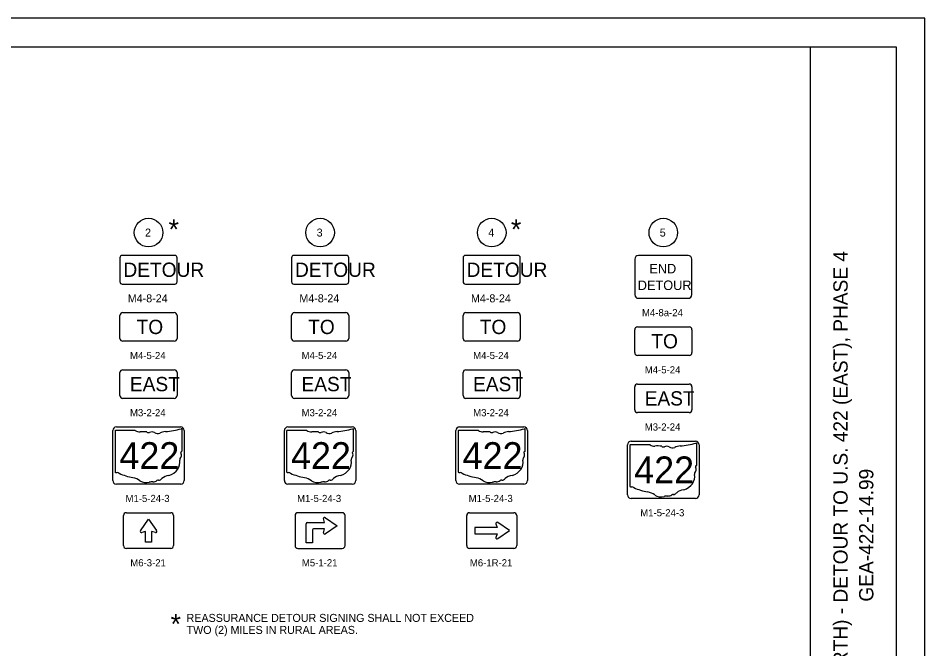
# Model space of a CAD drawing. Extents: x -0.3 to 34, y 0 to 22.
# Drawn here: x 18.15 to 34, y 10.97 to 22 of the extents above; entities that cross this region are included whole.
import ezdxf

# ---------------------------------------------------------------- set-up
doc = ezdxf.new("R2010")
doc.units = 0
for name, color, linetype in [('GM_X_Adjacent_County_Text', 7, 'Continuous'), ('GM_X_County', 7, 'Continuous'), ('GM_X_Minor_Lake_Text', 7, 'Continuous'), ('GM_X_Minor_River_Text', 7, 'Continuous'), ('GM_X_Section', 7, 'Continuous'), ('GM_X_Township', 7, 'Continuous')]:
    doc.layers.add(name, color=color, linetype=linetype)

msp = doc.modelspace()

# ---------------------------------------------------------------- linework, layer by layer
at = {"layer": 'GM_X_County'}
msp.add_line((32, 0.5), (32, 21.5), dxfattribs=at)
msp.add_lwpolyline([(1.5, 21.5), (33.5, 21.5), (33.5, 0.5), (1.5, 0.5)], close=True, dxfattribs=at)
at = {"layer": 'GM_X_Minor_Lake_Text'}
for centre in [(20.427, 18.249), (23.427, 18.249), (26.427, 18.249), (29.427, 18.249)]:
    msp.add_circle(centre, 0.25, dxfattribs=at)
at = {"layer": 'GM_X_Minor_River_Text'}
for p, q in [((19.977, 16.849), (20.877, 16.849)), ((22.977, 16.849), (23.877, 16.849)), ((25.977, 16.849), (26.877, 16.849)), ((19.927, 16.399), (19.927, 16.799)), ((20.927, 16.799), (20.927, 16.399)), ((22.927, 16.399), (22.927, 16.799)), ((23.927, 16.799), (23.927, 16.399)), ((25.927, 16.399), (25.927, 16.799)), ((26.927, 16.799), (26.927, 16.399)), ((28.927, 16.149), (28.927, 16.549)), ((28.977, 16.599), (29.877, 16.599)), ((29.927, 16.549), (29.927, 16.149)), ((20.877, 16.349), (19.977, 16.349)), ((23.877, 16.349), (22.977, 16.349)), ((26.877, 16.349), (25.977, 16.349)), ((29.877, 16.099), (28.977, 16.099)), ((19.927, 15.399), (19.927, 15.799)), ((19.977, 15.849), (20.877, 15.849)), ((20.927, 15.799), (20.927, 15.399)), ((22.927, 15.399), (22.927, 15.799)), ((22.977, 15.849), (23.877, 15.849)), ((23.927, 15.799), (23.927, 15.399)), ((25.927, 15.399), (25.927, 15.799)), ((25.977, 15.849), (26.877, 15.849)), ((26.927, 15.799), (26.927, 15.399)), ((28.927, 15.149), (28.927, 15.549)), ((28.977, 15.599), (29.877, 15.599)), ((29.927, 15.549), (29.927, 15.149)), ((20.877, 15.349), (19.977, 15.349)), ((23.877, 15.349), (22.977, 15.349)), ((26.877, 15.349), (25.977, 15.349)), ((29.877, 15.099), (28.977, 15.099)), ((19.841, 14.775), (19.841, 14.063)), ((20.196, 14.787), (19.852, 14.787)), ((21.013, 14.433), (21.013, 14.805)), ((22.841, 14.775), (22.841, 14.063)), ((23.196, 14.787), (22.852, 14.787)), ((24.013, 14.433), (24.013, 14.805)), ((25.841, 14.775), (25.841, 14.063)), ((26.196, 14.787), (25.852, 14.787)), ((27.013, 14.433), (27.013, 14.805)), ((21.013, 14.433), (21.013, 14.433)), ((24.013, 14.433), (24.013, 14.433)), ((27.013, 14.433), (27.013, 14.433)), ((28.841, 14.525), (28.841, 13.813)), ((29.196, 14.537), (28.852, 14.537)), ((30.013, 14.183), (30.013, 14.555)), ((30.013, 14.183), (30.013, 14.183)), ((20.039, 13.349), (20.814, 13.349)), ((23.814, 13.349), (23.039, 13.349)), ((26.039, 13.349), (26.814, 13.349)), ((19.989, 12.774), (19.989, 13.299)), ((20.285, 13.032), (20.427, 13.239)), ((20.427, 13.239), (20.567, 13.035)), ((20.864, 13.299), (20.864, 12.774)), ((22.989, 13.299), (22.989, 12.774)), ((23.208, 13.177), (23.505, 13.177)), ((23.208, 13.177), (23.208, 13.177)), ((23.505, 13.177), (23.484, 13.247)), ((23.52, 13.262), (23.724, 13.122)), ((23.864, 12.774), (23.864, 13.299)), ((25.989, 12.774), (25.989, 13.299)), ((26.739, 13.036), (26.532, 13.178)), ((26.864, 13.299), (26.864, 12.774)), ((20.372, 13.02), (20.308, 13)), ((20.372, 12.833), (20.372, 13.02)), ((20.546, 13), (20.481, 13.02)), ((20.481, 13.02), (20.481, 12.833)), ((23.185, 12.825), (23.185, 13.153)), ((23.294, 13.052), (23.294, 12.825)), ((23.505, 13.067), (23.31, 13.067)), ((23.484, 12.997), (23.505, 13.067)), ((23.724, 13.122), (23.52, 12.982)), ((26.521, 13.091), (26.13, 13.091)), ((26.13, 13.091), (26.13, 12.981)), ((26.501, 13.155), (26.521, 13.091)), ((26.535, 12.896), (26.739, 13.036)), ((26.13, 12.981), (26.521, 12.981)), ((26.521, 12.981), (26.501, 12.917)), ((20.814, 12.724), (20.039, 12.724)), ((20.481, 12.833), (20.372, 12.833)), ((23.039, 12.724), (23.814, 12.724)), ((23.294, 12.825), (23.185, 12.825)), ((26.814, 12.724), (26.039, 12.724))]:
    msp.add_line(p, q, dxfattribs=at)
for points in [[(19.927, 17.809), (19.927, 17.389)], [(20.887, 17.849), (19.967, 17.849)], [(20.927, 17.389), (20.927, 17.809)], [(22.927, 17.809), (22.927, 17.389)], [(23.887, 17.849), (22.967, 17.849)], [(23.927, 17.389), (23.927, 17.809)], [(25.927, 17.809), (25.927, 17.389)], [(26.887, 17.849), (25.967, 17.849)], [(26.927, 17.389), (26.927, 17.809)], [(28.927, 17.784), (28.927, 17.164)], [(29.862, 17.849), (28.992, 17.849)], [(29.927, 17.164), (29.927, 17.784)], [(19.967, 17.349), (20.887, 17.349)], [(22.967, 17.349), (23.887, 17.349)], [(25.967, 17.349), (26.887, 17.349)], [(28.992, 17.099), (29.862, 17.099)], [(19.802, 13.911), (19.802, 14.786)], [(19.864, 14.849), (20.989, 14.849)], [(21.052, 14.786), (21.052, 13.911)], [(22.802, 13.911), (22.802, 14.786)], [(22.864, 14.849), (23.989, 14.849)], [(24.052, 14.786), (24.052, 13.911)], [(25.802, 13.911), (25.802, 14.786)], [(25.864, 14.849), (26.989, 14.849)], [(27.052, 14.786), (27.052, 13.911)], [(28.864, 14.599), (29.989, 14.599)], [(28.802, 13.661), (28.802, 14.536)], [(30.052, 14.536), (30.052, 13.661)], [(20.989, 13.849), (19.864, 13.849)], [(23.989, 13.849), (22.864, 13.849)], [(26.989, 13.849), (25.864, 13.849)], [(29.989, 13.599), (28.864, 13.599)]]:
    msp.add_lwpolyline(points, dxfattribs=at)
for centre, radius, start, end in [((19.967, 17.809), 0.04, 90, 180), ((20.887, 17.809), 0.04, 0, 90), ((22.967, 17.809), 0.04, 90, 180), ((23.887, 17.809), 0.04, 0, 90), ((25.967, 17.809), 0.04, 90, 180), ((26.887, 17.809), 0.04, 0, 90), ((28.992, 17.784), 0.065, 90, 180), ((29.862, 17.784), 0.065, 0, 90), ((19.967, 17.389), 0.04, 180, 270), ((20.887, 17.389), 0.04, 270, 0), ((22.967, 17.389), 0.04, 180, 270), ((23.887, 17.389), 0.04, 270, 0), ((25.967, 17.389), 0.04, 180, 270), ((26.887, 17.389), 0.04, 270, 0), ((28.992, 17.164), 0.065, 180, 270), ((29.862, 17.164), 0.065, 270, 0), ((19.977, 16.799), 0.05, 90, 180), ((20.877, 16.799), 0.05, 0, 90), ((22.977, 16.799), 0.05, 90, 180), ((23.877, 16.799), 0.05, 0, 90), ((25.977, 16.799), 0.05, 90, 180), ((26.877, 16.799), 0.05, 0, 90), ((28.977, 16.549), 0.05, 90, 180), ((29.877, 16.549), 0.05, 0, 90), ((19.977, 16.399), 0.05, 180, 270), ((20.877, 16.399), 0.05, 270, 360), ((22.977, 16.399), 0.05, 180, 270), ((23.877, 16.399), 0.05, 270, 360), ((25.977, 16.399), 0.05, 180, 270), ((26.877, 16.399), 0.05, 270, 360), ((28.977, 16.149), 0.05, 180, 270), ((29.877, 16.149), 0.05, 270, 360), ((19.977, 15.799), 0.05, 90, 180), ((20.877, 15.799), 0.05, 0, 90), ((22.977, 15.799), 0.05, 90, 180), ((23.877, 15.799), 0.05, 0, 90), ((25.977, 15.799), 0.05, 90, 180), ((26.877, 15.799), 0.05, 0, 90), ((28.977, 15.549), 0.05, 90, 180), ((29.877, 15.549), 0.05, 0, 90), ((19.977, 15.399), 0.05, 180, 270), ((20.877, 15.399), 0.05, 270, 0), ((22.977, 15.399), 0.05, 180, 270), ((23.877, 15.399), 0.05, 270, 0), ((25.977, 15.399), 0.05, 180, 270), ((26.877, 15.399), 0.05, 270, 0), ((28.977, 15.149), 0.05, 180, 270), ((29.877, 15.149), 0.05, 270, 0), ((19.864, 14.786), 0.0625, 90, 180), ((20.989, 14.786), 0.0625, 0, 90), ((22.864, 14.786), 0.0625, 90, 180), ((23.989, 14.786), 0.0625, 0, 90), ((25.864, 14.786), 0.0625, 90, 180), ((26.989, 14.786), 0.0625, 0, 90), ((28.864, 14.536), 0.0625, 90, 180), ((29.989, 14.536), 0.0625, 0, 90), ((19.864, 13.911), 0.0625, 180, 270), ((20.989, 13.911), 0.0625, 270, 0), ((22.864, 13.911), 0.0625, 180, 270), ((23.989, 13.911), 0.0625, 270, 0), ((25.864, 13.911), 0.0625, 180, 270), ((26.989, 13.911), 0.0625, 270, 0), ((28.864, 13.661), 0.0625, 180, 270), ((29.989, 13.661), 0.0625, 270, 0), ((20.039, 13.299), 0.05, 90, 180), ((20.814, 13.299), 0.05, 0, 90), ((23.039, 13.299), 0.05, 90, 180), ((23.814, 13.299), 0.05, 0, 90), ((26.039, 13.299), 0.05, 90, 180), ((26.814, 13.299), 0.05, 0, 90), ((23.208, 13.153), 0.0234, 90, 180), ((23.505, 13.247), 0.0209, 45.0001, 179.9983), ((26.521, 13.161), 0.0209, 55.4112, 197.2046), ((20.302, 13.02), 0.0209, 145.4112, 287.2046), ((20.552, 13.02), 0.0209, 252.7954, 45.0096), ((23.31, 13.052), 0.0156, 90, 180), ((23.505, 12.997), 0.0209, 179.9983, 314.9999), ((26.521, 12.911), 0.0209, 162.7954, 315.0096), ((20.039, 12.774), 0.05, 180, 270), ((20.814, 12.774), 0.05, 270, 0), ((23.039, 12.774), 0.05, 180, 270), ((23.814, 12.774), 0.05, 270, 0), ((26.039, 12.774), 0.05, 180, 270), ((26.814, 12.774), 0.05, 270, 360)]:
    msp.add_arc(centre, radius, start, end, dxfattribs=at)
for centre, major_axis, start_param, end_param in [((19.854, 14.776), (0.0136, 0), 1.712693, 3.28349), ((20.277, 14.87), (0.132, 0), 4.042523, 4.731795), ((20.321, 14.388), (0.473, 0), 1.404758, 1.657858), ((20.428, 14.78), (0.038, 0), 3.836095, 5.185415), ((20.484, 14.698), (0.079, 0), 0.950623, 2.079405), ((20.586, 14.811), (0.095, 0), 4.081561, 5.145723), ((20.754, 14.57), (0.25, 0), 1.699011, 2.107814), ((20.595, 15.757), (1.243, 0), 4.814394, 5.042369), ((21, 14.806), (0.013, 0), 6.141152, 7.989035), ((22.854, 14.776), (0.0136, 0), 1.712693, 3.28349), ((23.277, 14.87), (0.132, 0), 4.042523, 4.731795), ((23.321, 14.388), (0.473, 0), 1.404758, 1.657858), ((23.428, 14.78), (0.038, 0), 3.836095, 5.185415), ((23.484, 14.698), (0.079, 0), 0.950623, 2.079405), ((23.586, 14.811), (0.095, 0), 4.081561, 5.145723), ((23.754, 14.57), (0.25, 0), 1.699011, 2.107814), ((23.595, 15.757), (1.243, 0), 4.814394, 5.042369), ((24, 14.806), (0.013, 0), 6.141152, 7.989035), ((25.854, 14.776), (0.0136, 0), 1.712693, 3.28349), ((26.277, 14.87), (0.132, 0), 4.042523, 4.731795), ((26.321, 14.388), (0.473, 0), 1.404758, 1.657858), ((26.428, 14.78), (0.038, 0), 3.836095, 5.185415), ((26.484, 14.698), (0.079, 0), 0.950623, 2.079405), ((26.586, 14.811), (0.095, 0), 4.081561, 5.145723), ((26.754, 14.57), (0.25, 0), 1.699011, 2.107814), ((26.595, 15.757), (1.243, 0), 4.814394, 5.042369), ((27, 14.806), (0.013, 0), 6.141152, 7.989035), ((20.999, 14.431), (0.014, 0), 5.05454, 6.418171), ((23.999, 14.431), (0.014, 0), 5.05454, 6.418171), ((26.999, 14.431), (0.014, 0), 5.05454, 6.418171), ((28.854, 14.526), (0.0136, 0), 1.712693, 3.28349), ((29.277, 14.62), (0.132, 0), 4.042523, 4.731795), ((29.321, 14.138), (0.473, 0), 1.404758, 1.657858), ((29.428, 14.53), (0.038, 0), 3.836095, 5.185415), ((29.484, 14.448), (0.079, 0), 0.950623, 2.079405), ((29.586, 14.561), (0.095, 0), 4.081561, 5.145723), ((29.754, 14.32), (0.25, 0), 1.699011, 2.107814), ((29.595, 15.507), (1.243, 0), 4.814394, 5.042369), ((30, 14.556), (0.013, 0), 6.141152, 7.989035), ((20.665, 14.229), (0.311, 0), 5.101752, 6.440018), ((21.059, 14.277), (0.0882, 0), 2.387724, 3.262537), ((21.01, 14.405), (0.0202, 0), 1.883978, 3.671073), ((20.881, 14.358), (0.121, 0), 5.934695, 6.695948), ((23.665, 14.229), (0.311, 0), 5.101752, 6.440018), ((24.059, 14.277), (0.0882, 0), 2.387724, 3.262537), ((24.01, 14.405), (0.0202, 0), 1.883978, 3.671073), ((23.881, 14.358), (0.121, 0), 5.934695, 6.695948), ((26.665, 14.229), (0.311, 0), 5.101752, 6.440018), ((27.059, 14.277), (0.0882, 0), 2.387724, 3.262537), ((27.01, 14.405), (0.0202, 0), 1.883978, 3.671073), ((26.881, 14.358), (0.121, 0), 5.934695, 6.695948), ((30.01, 14.155), (0.0202, 0), 1.883978, 3.671073), ((29.881, 14.108), (0.121, 0), 5.934695, 6.695948), ((29.999, 14.181), (0.014, 0), 5.05454, 6.418171), ((19.854, 14.062), (0.0137, 0), 3.00124, 4.508301), ((19.856, 14.135), (0.105, 0), 4.665946, 4.897461), ((19.878, 14.022), (0.0377, 0), 0.519207, 1.627899), ((20.354, 14.662), (0.897, 0), 4.195997, 4.488961), ((20.086, 13.744), (0.281, 0), 0.823519, 1.323587), ((20.796, 13.864), (0.17, 0), 1.647645, 2.488434), ((22.854, 14.062), (0.0137, 0), 3.00124, 4.508301), ((22.856, 14.135), (0.105, 0), 4.665946, 4.897461), ((22.878, 14.022), (0.0377, 0), 0.519207, 1.627899), ((23.354, 14.662), (0.897, 0), 4.195997, 4.488961), ((23.086, 13.744), (0.281, 0), 0.823519, 1.323587), ((23.796, 13.864), (0.17, 0), 1.647645, 2.488434), ((25.854, 14.062), (0.0137, 0), 3.00124, 4.508301), ((25.856, 14.135), (0.105, 0), 4.665946, 4.897461), ((25.878, 14.022), (0.0377, 0), 0.519207, 1.627899), ((26.354, 14.662), (0.897, 0), 4.195997, 4.488961), ((26.086, 13.744), (0.281, 0), 0.823519, 1.323587), ((26.796, 13.864), (0.17, 0), 1.647645, 2.488434), ((29.665, 13.979), (0.311, 0), 5.101752, 6.440018), ((30.059, 14.027), (0.0882, 0), 2.387724, 3.262537), ((20.39, 14.019), (0.178, 0), 4.026481, 4.996735), ((20.493, 13.773), (0.146, 0), 1.495662, 1.94098), ((20.506, 13.966), (0.0949, 0), 4.691044, 5.507374), ((20.592, 13.897), (0.0267, 0), 1.147584, 2.315152), ((20.58, 13.994), (0.1, 0), 4.937069, 5.64225), ((23.39, 14.019), (0.178, 0), 4.026481, 4.996735), ((23.493, 13.773), (0.146, 0), 1.495662, 1.94098), ((23.506, 13.966), (0.0949, 0), 4.691044, 5.507374), ((23.592, 13.897), (0.0267, 0), 1.147584, 2.315152), ((23.58, 13.994), (0.1, 0), 4.937069, 5.64225), ((26.39, 14.019), (0.178, 0), 4.026481, 4.996735), ((26.493, 13.773), (0.146, 0), 1.495662, 1.94098), ((26.506, 13.966), (0.0949, 0), 4.691044, 5.507374), ((26.592, 13.897), (0.0267, 0), 1.147584, 2.315152), ((26.58, 13.994), (0.1, 0), 4.937069, 5.64225), ((28.854, 13.812), (0.0137, 0), 3.00124, 4.508301), ((28.856, 13.885), (0.105, 0), 4.665946, 4.897461), ((28.878, 13.772), (0.0377, 0), 0.519207, 1.627899), ((29.354, 14.412), (0.897, 0), 4.195997, 4.488961), ((29.086, 13.494), (0.281, 0), 0.823519, 1.323587), ((29.39, 13.769), (0.178, 0), 4.026481, 4.996735), ((29.493, 13.523), (0.146, 0), 1.495662, 1.94098), ((29.506, 13.716), (0.0949, 0), 4.691044, 5.507374), ((29.592, 13.647), (0.0267, 0), 1.147584, 2.315152), ((29.58, 13.744), (0.1, 0), 4.937069, 5.64225), ((29.796, 13.614), (0.17, 0), 1.647645, 2.488434)]:
    msp.add_ellipse(centre, major_axis=major_axis, ratio=0.8, start_param=start_param, end_param=end_param, dxfattribs=at)
at = {"layer": 'GM_X_Section'}
msp.add_lwpolyline([(0, 0), (34, 0), (34, 22), (0, 22)], close=True, dxfattribs=at)

# ---------------------------------------------------------------- texts
at = {"layer": 'GM_X_Adjacent_County_Text'}
for s, height, p in [('*', 0.35, (20.777, 18.131)), ('*', 0.35, (26.763, 18.131)), ('*', 0.35, (20.812, 11.229)), ('REASSURANCE DETOUR SIGNING SHALL NOT EXCEED', 0.14, (21.092, 11.439)), ('TWO (2) MILES IN RURAL AREAS.', 0.14, (21.092, 11.229))]:
    msp.add_text(s, height=height, dxfattribs=at).set_placement(p)
at = {"layer": 'GM_X_Minor_Lake_Text'}
for s, height, p in [('2', 0.14, (20.366, 18.179)), ('3', 0.14, (23.366, 18.179)), ('4', 0.14, (26.367, 18.179)), ('5', 0.14, (29.365, 18.179)), ('M4-8-24', 0.14, (20.064, 17.029)), ('M4-8-24', 0.14, (23.064, 17.029)), ('M4-8-24', 0.14, (26.064, 17.029)), ('M4-8a-24', 0.125, (29.054, 16.786)), ('M4-5-24', 0.125, (20.103, 16.036)), ('M4-5-24', 0.125, (23.103, 16.036)), ('M4-5-24', 0.125, (26.103, 16.036)), ('M4-5-24', 0.125, (29.103, 15.786)), ('M3-2-24', 0.125, (20.103, 15.036)), ('M3-2-24', 0.125, (23.103, 15.036)), ('M3-2-24', 0.125, (26.103, 15.036)), ('M3-2-24', 0.125, (29.103, 14.786)), ('M1-5-24-3', 0.125, (20.024, 13.536)), ('M1-5-24-3', 0.125, (23.024, 13.536)), ('M1-5-24-3', 0.125, (26.024, 13.536)), ('M1-5-24-3', 0.125, (29.024, 13.286)), ('M6-3-21', 0.125, (20.108, 12.411)), ('M5-1-21', 0.125, (23.108, 12.411)), ('M6-1R-21', 0.125, (26.045, 12.411))]:
    msp.add_text(s, height=height, dxfattribs=at).set_placement(p)
at = {"layer": 'GM_X_Minor_River_Text'}
for s, height, p in [('DETOUR', 0.25, (19.988, 17.474)), ('DETOUR', 0.25, (22.988, 17.474)), ('DETOUR', 0.25, (25.988, 17.474)), ('END', 0.1667, (29.182, 17.535)), ('DETOUR', 0.1667, (28.98, 17.244)), ('TO', 0.25, (20.218, 16.474)), ('TO', 0.25, (23.218, 16.474)), ('TO', 0.25, (26.218, 16.474)), ('TO', 0.25, (29.218, 16.224)), ('EAST', 0.25, (20.101, 15.474)), ('EAST', 0.25, (23.101, 15.474)), ('EAST', 0.25, (26.101, 15.474)), ('EAST', 0.25, (29.101, 15.224)), ('422', 0.4688, (19.919, 14.114)), ('422', 0.4688, (22.919, 14.114)), ('422', 0.4688, (25.919, 14.114)), ('422', 0.4688, (28.919, 13.864))]:
    msp.add_text(s, height=height, dxfattribs=at).set_placement(p)
at = {"layer": 'GM_X_Township'}
for s, p in [('MUMFORD RD (NORTH) - DETOUR TO U.S. 422 (EAST), PHASE 4', (32.65, 7.655)), ('GEA-422-14.99', (33.1, 11.794))]:
    msp.add_text(s, height=0.25, rotation=90, dxfattribs=at).set_placement(p)

doc.saveas('drawing.dxf')
